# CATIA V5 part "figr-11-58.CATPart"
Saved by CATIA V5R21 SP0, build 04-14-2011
Part number: Part1
Bounding box of the stored display mesh (mm): x -59.829 to 59.829, y -71.429 to 72.174, z -61 to 76
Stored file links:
  D:\CATIA V5R21 E-RESOURCES\CATIA-V5R21\catia-v5r21-prt\c11-catia-v5r21-prt\c11-catia-v5r21-figr-11-58.CATPart
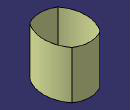
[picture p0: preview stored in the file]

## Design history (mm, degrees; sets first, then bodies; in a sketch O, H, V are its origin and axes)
Set1
  Extrude1: Element1 Sketch1, Lim1 76, Lim2 61, Direction xy-plane
Body1 (main body)
  Sketch1 on xy-plane, origin (0, 0, 0), H (0, 1, 0), V (-1, 0, 0)
    arc A1 centre (0, -40) radius 100 from (-60, 40) to (60, 40) cw
    point P2 (0, 60)
    point P3 (-60, 40)
    point P4 (60, 40)
    axis line L1 (-90, 0) -> (80, 0)
    point P6 (80, 0)
    point P7 (60, -40)
    point P8 (-60, -40)
    arc A2 centre (0, 40) radius 100 from (-60, -40) to (60, -40) ccw
    arc A3 centre (4.2857, 0) radius 75.7143 from (-60, 40) to (-60, -40) ccw
    arc A4 centre (0.3727, 0) radius 71.8012 from (60, -40) to (60, 40) ccw
    coincidence: A1 P2, P2 V, A3 P6
    horizontal: L1 H
    symmetry: P4 P7 L1, P3 P8 L1, A1 A2 L1
    tangency: A4 A3
  Sketch2 on xy-plane, origin (0, 0, 0), H (1, 0, 0), V (0, 1, 0)
    spline S1 through (80, 90) (60, 60) (70, 0) (50, -50) (50, -80)
    point P1 (70, 0)
    coincidence: P1 H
